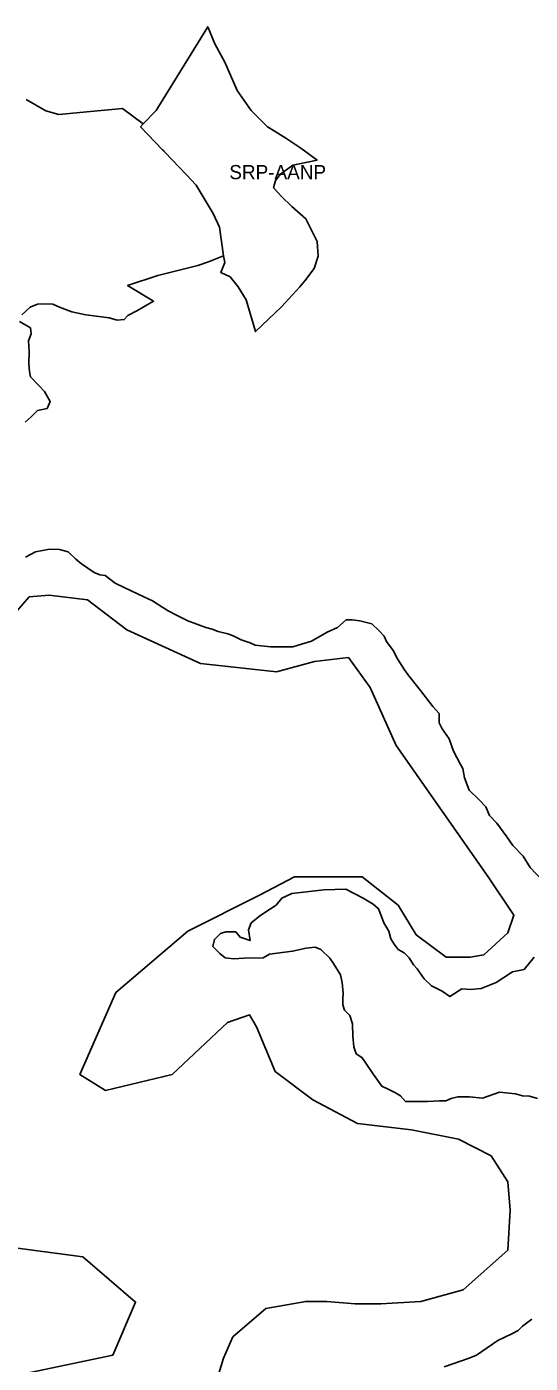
# Model space of a CAD drawing. Extents: x 598968 to 613553, y 4409678 to 4430833.
# Drawn here: x 604746 to 605173, y 4417266 to 4418399 of the extents above; entities that cross this region are included whole.
import ezdxf

# ---------------------------------------------------------------- set-up
doc = ezdxf.new("R2010")
doc.units = 0
for name, color, linetype in [('Sòl Rústic Comú', 7, 'Continuous'), ('Sòl Rústic Protegit', 7, 'Continuous'), ('Sòl Rústic Protegit - Alt Nivell de Protecció', 7, 'Continuous')]:
    doc.layers.add(name, color=color, linetype=linetype)

msp = doc.modelspace()

# ---------------------------------------------------------------- linework, layer by layer
at = {"layer": 'Sòl Rústic Comú'}
msp.add_lwpolyline([(604696.9791, 4417247.1936), (604818.6681, 4417272.6938), (604837.8559, 4417317.694), (604793.0431, 4417356.194), (604696.9797, 4417368.6938)], dxfattribs=at)
at = {"layer": 'Sòl Rústic Protegit'}
for points in [[(604745.1713, 4418337.1948), (604761.8589, 4418327.6948), (604772.7965, 4418324.6948), (604799.5469, 4418327.1948), (604826.7971, 4418329.6948), (604844.2347, 4418316.6948), (604855.3677, 4418328.0102), (604899.1177, 4418399.0102), (604905.1175, 4418384.5102), (604913.6801, 4418369.0102), (604923.9925, 4418345.0102), (604935.9927, 4418328.0102), (604949.7427, 4418314.0102), (604956.1633, 4418310.0588), (604965.1801, 4418304.5102), (604978.0551, 4418296.0102), (604985.3841, 4418290.6556), (604991.7427, 4418286.0102), (604974.0359, 4418282.1352), (604971.1799, 4418281.5102), (604960.8677, 4418274.0102), (604956.6177, 4418268.5102), (604954.8677, 4418262.5102), (604958.9113, 4418258.0988), (604961.7425, 4418255.0102), (604970.3051, 4418246.5102), (604982.3051, 4418236.0102), (604991.7427, 4418217.0102), (604992.6177, 4418204.5102), (604989.1801, 4418194.0102), (604981.4927, 4418183.5102), (604977.1799, 4418178.5102), (604961.7425, 4418161.5102), (604939.4299, 4418140.5102), (604931.6799, 4418167.5102), (604924.8677, 4418178.5102), (604917.9927, 4418187.0102), (604910.2427, 4418190.5102), (604913.6801, 4418199.0102), (604912.4851, 4418204.6948), (604899.7973, 4418199.6948), (604890.6097, 4418196.6948), (604856.7343, 4418188.1948), (604831.0465, 4418179.6948), (604853.1093, 4418166.1948), (604839.0465, 4418158.1948), (604831.2965, 4418154.1948), (604828.2965, 4418150.6946), (604822.3589, 4418150.1946), (604815.4839, 4418152.1946), (604795.7961, 4418154.6946), (604783.7959, 4418157.1946), (604773.3585, 4418161.1946), (604767.6709, 4418163.6946), (604761.4833, 4418164.1946), (604754.8583, 4418163.6946), (604748.5457, 4418161.1946), (604741.4831, 4418154.6946)], [(604741.4831, 4418154.6946), (604748.5457, 4418161.1946), (604754.8583, 4418163.6946), (604761.4833, 4418164.1946), (604767.6709, 4418163.6946), (604773.3585, 4418161.1946), (604783.7959, 4418157.1946), (604795.7961, 4418154.6946), (604815.4839, 4418152.1946), (604822.3589, 4418150.1946), (604828.2965, 4418150.6946), (604831.2965, 4418154.1948), (604839.0465, 4418158.1948), (604853.1093, 4418166.1948), (604831.0465, 4418179.6948), (604856.7343, 4418188.1948), (604890.6097, 4418196.6948), (604899.7973, 4418199.6948), (604912.4851, 4418204.6948), (604909.0475, 4418229.1948), (604903.8113, 4418240.7756), (604889.2975, 4418264.6948), (604881.0665, 4418273.3832), (604862.7125, 4418292.6684), (604861.9603, 4418293.4588), (604861.4329, 4418294.013), (604860.7945, 4418294.6838), (604842.1097, 4418314.1948), (604844.2347, 4418316.6948), (604826.7971, 4418329.6948), (604799.5469, 4418327.1948), (604772.7965, 4418324.6948), (604761.8589, 4418327.6948), (604745.1713, 4418337.1948)], [(604744.3577, 4418063.6944), (604749.2953, 4418068.1946), (604754.7953, 4418073.6946), (604762.7955, 4418075.1946), (604765.4205, 4418081.1946), (604760.6079, 4418089.6946), (604755.8579, 4418094.6946), (604748.8579, 4418102.1946), (604747.8579, 4418106.6946), (604747.4829, 4418113.1946), (604747.7955, 4418123.6946), (604747.0455, 4418132.6946), (604749.4205, 4418138.6946), (604748.9205, 4418143.6946), (604739.5455, 4418149.1946)], [(604739.5455, 4418149.1946), (604748.9205, 4418143.6946), (604749.4205, 4418138.6946), (604747.0455, 4418132.6946), (604747.7955, 4418123.6946), (604747.4829, 4418113.1946), (604747.8579, 4418106.6946), (604748.8579, 4418102.1946), (604755.8579, 4418094.6946), (604760.6079, 4418089.6946), (604765.4205, 4418081.1946), (604762.7955, 4418075.1946), (604754.7953, 4418073.6946), (604749.2953, 4418068.1946), (604744.3577, 4418063.6944)], [(605182.9859, 4417675.1948), (605172.5483, 4417686.1948), (605166.5483, 4417695.6948), (605157.7981, 4417704.6948), (605152.7357, 4417712.1948), (605144.2981, 4417723.6948), (605138.1105, 4417730.1948), (605134.7981, 4417737.6948), (605129.0481, 4417743.6948), (605120.7979, 4417751.6948), (605116.9229, 4417762.1948), (605115.3605, 4417770.1948), (605112.9855, 4417774.1948), (605107.3605, 4417784.6948), (605103.9229, 4417795.1948), (605097.7355, 4417803.6948), (605095.2979, 4417808.6948), (605095.2355, 4417816.6948), (605089.9229, 4417822.6948), (605079.5479, 4417836.1948), (605069.6729, 4417848.6948), (605065.9853, 4417853.6948), (605060.1103, 4417863.1948), (605056.2353, 4417870.1948), (605050.6727, 4417877.6948), (605048.7977, 4417882.1948), (605044.3601, 4417886.6948), (605038.1727, 4417892.6948), (605027.9225, 4417895.1948), (605021.4849, 4417896.1948), (605016.3599, 4417896.1948), (605009.1723, 4417889.6948), (605000.2347, 4417885.6946), (604986.9221, 4417878.1946), (604975.6719, 4417874.6946), (604971.2343, 4417873.1946), (604964.6093, 4417873.1946), (604952.2341, 4417873.1946), (604939.3591, 4417874.6946), (604935.0465, 4417876.6946), (604927.2965, 4417879.1946), (604920.6713, 4417882.6946), (604915.9839, 4417884.1946), (604908.0463, 4417886.1946), (604902.7337, 4417888.1946), (604897.5461, 4417889.6946), (604882.2961, 4417895.1946), (604872.6709, 4417900.1946), (604865.5459, 4417903.6946), (604860.9209, 4417906.6946), (604852.2957, 4417912.1946), (604844.7957, 4417915.6944), (604828.1081, 4417923.6944), (604820.5455, 4417927.1944), (604812.2329, 4417933.6944), (604807.4829, 4417934.1944), (604802.6703, 4417936.1944), (604792.1077, 4417943.6944), (604787.1077, 4417947.6944), (604780.7327, 4417953.6944), (604773.4827, 4417955.6944), (604764.9825, 4417956.1944), (604752.9199, 4417953.6944), (604744.6697, 4417949.1944)], [(604744.6697, 4417949.1944), (604752.9199, 4417953.6944), (604764.9825, 4417956.1944), (604773.4827, 4417955.6944), (604780.7327, 4417953.6944), (604787.1077, 4417947.6944), (604792.1077, 4417943.6944), (604802.6703, 4417936.1944), (604807.4829, 4417934.1944), (604812.2329, 4417933.6944), (604820.5455, 4417927.1944), (604828.1081, 4417923.6944), (604844.7957, 4417915.6944), (604852.2957, 4417912.1946), (604860.9209, 4417906.6946), (604865.5459, 4417903.6946), (604872.6709, 4417900.1946), (604882.2961, 4417895.1946), (604897.5461, 4417889.6946), (604902.7337, 4417888.1946), (604908.0463, 4417886.1946), (604915.9839, 4417884.1946), (604920.6713, 4417882.6946), (604927.2965, 4417879.1946), (604935.0465, 4417876.6946), (604939.3591, 4417874.6946), (604952.2341, 4417873.1946), (604964.6093, 4417873.1946), (604971.2343, 4417873.1946), (604975.6719, 4417874.6946), (604986.9221, 4417878.1946), (605000.2347, 4417885.6946), (605009.1723, 4417889.6948), (605016.3599, 4417896.1948), (605021.4849, 4417896.1948), (605027.9225, 4417895.1948), (605038.1727, 4417892.6948), (605044.3601, 4417886.6948), (605048.7977, 4417882.1948), (605050.6727, 4417877.6948), (605056.2353, 4417870.1948), (605060.1103, 4417863.1948), (605065.9853, 4417853.6948), (605069.6729, 4417848.6948), (605079.5479, 4417836.1948), (605089.9229, 4417822.6948), (605095.2355, 4417816.6948), (605095.2979, 4417808.6948), (605097.7355, 4417803.6948), (605103.9229, 4417795.1948), (605107.3605, 4417784.6948), (605112.9855, 4417774.1948), (605115.3605, 4417770.1948), (605116.9229, 4417762.1948), (605120.7979, 4417751.6948), (605129.0481, 4417743.6948), (605134.7981, 4417737.6948), (605138.1105, 4417730.1948), (605144.2981, 4417723.6948), (605152.7357, 4417712.1948), (605157.7981, 4417704.6948), (605166.5483, 4417695.6948), (605172.5483, 4417686.1948), (605182.9859, 4417675.1948)], [(604736.9821, 4417903.1944), (604747.7323, 4417915.6944), (604764.6073, 4417917.1944), (604797.1703, 4417913.1944), (604830.4829, 4417887.6944), (604893.0461, 4417859.1946), (604957.3591, 4417852.1946), (604989.4845, 4417860.6946), (605018.2973, 4417864.1946), (605036.8599, 4417838.6946), (605058.8599, 4417789.6946), (605136.7353, 4417678.1946), (605158.6729, 4417645.6946), (605153.6103, 4417630.6946), (605133.2975, 4417612.1946), (605121.4849, 4417610.1946), (605101.1723, 4417610.1946), (605075.7971, 4417629.1946), (605060.5469, 4417654.1946), (605030.1093, 4417678.1946), (605003.0465, 4417678.1944), (604972.6087, 4417678.1944), (604943.0457, 4417662.6944), (604882.1075, 4417632.1942), (604821.1691, 4417580.1942), (604790.6687, 4417510.694), (604812.4187, 4417497.194), (604869.0445, 4417510.6942), (604915.9201, 4417554.6942), (604934.3579, 4417561.1942), (604940.3579, 4417551.1942), (604956.2953, 4417513.1942), (604988.1705, 4417489.1942), (605025.9835, 4417469.1944), (605071.7963, 4417463.6944), (605111.6093, 4417455.6944), (605139.4845, 4417441.6944), (605153.4221, 4417419.6944), (605155.4219, 4417395.6944), (605153.4219, 4417361.6944), (605115.6089, 4417328.1944), (605079.7333, 4417318.1942), (605045.9205, 4417316.1942), (605023.9829, 4417316.1942), (605000.1075, 4417318.1942), (604982.1699, 4417318.1942), (604948.2945, 4417312.194), (604920.4191, 4417288.194), (604912.4815, 4417270.194), (604904.5437, 4417244.194)], [(604904.5437, 4417244.194), (604912.4815, 4417270.194), (604920.4191, 4417288.194), (604948.2945, 4417312.194), (604982.1699, 4417318.1942), (605000.1075, 4417318.1942), (605023.9829, 4417316.1942), (605045.9205, 4417316.1942), (605079.7333, 4417318.1942), (605115.6089, 4417328.1944), (605153.4219, 4417361.6944), (605155.4219, 4417395.6944), (605153.4221, 4417419.6944), (605139.4845, 4417441.6944), (605111.6093, 4417455.6944), (605071.7963, 4417463.6944), (605025.9835, 4417469.1944), (604988.1705, 4417489.1942), (604956.2953, 4417513.1942), (604940.3579, 4417551.1942), (604934.3579, 4417561.1942), (604915.9201, 4417554.6942), (604869.0445, 4417510.6942), (604812.4187, 4417497.194), (604790.6687, 4417510.694), (604821.1691, 4417580.1942), (604882.1075, 4417632.1942), (604943.0457, 4417662.6944), (604972.6087, 4417678.1944), (605003.0465, 4417678.1944), (605030.1093, 4417678.1946), (605060.5469, 4417654.1946), (605075.7971, 4417629.1946), (605101.1723, 4417610.1946), (605121.4849, 4417610.1946), (605133.2975, 4417612.1946), (605153.6103, 4417630.6946), (605158.6729, 4417645.6946), (605136.7353, 4417678.1946), (605058.8599, 4417789.6946), (605036.8599, 4417838.6946), (605018.2973, 4417864.1946), (604989.4845, 4417860.6946), (604957.3591, 4417852.1946), (604893.0461, 4417859.1946), (604830.4829, 4417887.6944), (604797.1703, 4417913.1944), (604764.6073, 4417917.1944), (604747.7323, 4417915.6944), (604736.9821, 4417903.1944)], [(605178.6725, 4417490.1946), (605171.7975, 4417492.1946), (605165.9849, 4417492.6946), (605159.9849, 4417494.1946), (605154.6099, 4417494.6946), (605146.3597, 4417495.6946), (605132.1721, 4417490.6944), (605121.1095, 4417491.6944), (605111.1093, 4417491.6944), (605105.4843, 4417490.1944), (605101.0467, 4417488.1944), (605095.5467, 4417488.1944), (605085.4841, 4417487.6944), (605079.7341, 4417487.6944), (605066.8589, 4417487.6944), (605062.4213, 4417492.6944), (605058.2963, 4417495.1944), (605051.9837, 4417498.1944), (605046.6087, 4417500.6944), (605039.6713, 4417510.6944), (605032.6711, 4417521.1944), (605029.8587, 4417525.1944), (605024.9837, 4417528.1944), (605022.8587, 4417534.1944), (605022.0461, 4417543.1944), (605021.7337, 4417553.6944), (605019.6711, 4417560.6944), (605015.1087, 4417565.1944), (605013.7337, 4417569.6944), (605013.7337, 4417574.6944), (605013.8587, 4417579.6944), (605013.0463, 4417588.6944), (605011.6713, 4417595.1944), (605005.6713, 4417604.6944), (605002.5461, 4417609.1944), (604994.9837, 4417616.6944), (604990.1087, 4417618.6944), (604982.4211, 4417617.6944), (604970.9833, 4417615.1944), (604951.4207, 4417612.6944), (604946.1081, 4417609.6944), (604929.9829, 4417609.1944), (604920.7953, 4417608.6944), (604913.9827, 4417609.6944), (604909.3577, 4417613.1944), (604903.4827, 4417619.1944), (604904.7953, 4417625.1944), (604909.8579, 4417630.1944), (604914.4829, 4417631.6944), (604922.8579, 4417631.6944), (604926.4829, 4417627.1944), (604934.9205, 4417624.1944), (604933.5455, 4417633.1944), (604935.9207, 4417639.1944), (604943.9833, 4417645.6944), (604952.1709, 4417651.1944), (604956.9833, 4417654.1944), (604961.8585, 4417660.1944), (604970.2961, 4417664.1944), (604997.5463, 4417667.1944), (605016.2965, 4417667.6946), (605030.9841, 4417660.1946), (605039.4217, 4417655.1946), (605043.8593, 4417651.1946), (605046.4217, 4417644.6946), (605048.4843, 4417639.1946), (605052.7343, 4417632.1946), (605054.2967, 4417625.6946), (605057.1719, 4417621.1946), (605060.5469, 4417616.6946), (605065.6719, 4417613.6946), (605069.9845, 4417609.6946), (605073.4845, 4417603.6946), (605076.6095, 4417600.1946), (605082.6719, 4417591.6946), (605088.7971, 4417585.6946), (605097.9221, 4417581.1946), (605104.3597, 4417576.6946), (605114.6097, 4417583.1946), (605121.9849, 4417582.6946), (605131.0475, 4417583.6946), (605143.5475, 4417588.6946), (605157.4853, 4417597.6946), (605167.2353, 4417599.6946), (605175.7355, 4417610.1946)], [(605175.7355, 4417610.1946), (605167.2353, 4417599.6946), (605157.4853, 4417597.6946), (605143.5475, 4417588.6946), (605131.0475, 4417583.6946), (605121.9849, 4417582.6946), (605114.6097, 4417583.1946), (605104.3597, 4417576.6946), (605097.9221, 4417581.1946), (605088.7971, 4417585.6946), (605082.6719, 4417591.6946), (605076.6095, 4417600.1946), (605073.4845, 4417603.6946), (605069.9845, 4417609.6946), (605065.6719, 4417613.6946), (605060.5469, 4417616.6946), (605057.1719, 4417621.1946), (605054.2967, 4417625.6946), (605052.7343, 4417632.1946), (605048.4843, 4417639.1946), (605046.4217, 4417644.6946), (605043.8593, 4417651.1946), (605039.4217, 4417655.1946), (605030.9841, 4417660.1946), (605016.2965, 4417667.6946), (604997.5463, 4417667.1944), (604970.2961, 4417664.1944), (604961.8585, 4417660.1944), (604956.9833, 4417654.1944), (604952.1709, 4417651.1944), (604943.9833, 4417645.6944), (604935.9207, 4417639.1944), (604933.5455, 4417633.1944), (604934.9205, 4417624.1944), (604926.4829, 4417627.1944), (604922.8579, 4417631.6944), (604914.4829, 4417631.6944), (604909.8579, 4417630.1944), (604904.7953, 4417625.1944), (604903.4827, 4417619.1944), (604909.3577, 4417613.1944), (604913.9827, 4417609.6944), (604920.7953, 4417608.6944), (604929.9829, 4417609.1944), (604946.1081, 4417609.6944), (604951.4207, 4417612.6944), (604970.9833, 4417615.1944), (604982.4211, 4417617.6944), (604990.1087, 4417618.6944), (604994.9837, 4417616.6944), (605002.5461, 4417609.1944), (605005.6713, 4417604.6944), (605011.6713, 4417595.1944), (605013.0463, 4417588.6944), (605013.8587, 4417579.6944), (605013.7337, 4417574.6944), (605013.7337, 4417569.6944), (605015.1087, 4417565.1944), (605019.6711, 4417560.6944), (605021.7337, 4417553.6944), (605022.0461, 4417543.1944), (605022.8587, 4417534.1944), (605024.9837, 4417528.1944), (605029.8587, 4417525.1944), (605032.6711, 4417521.1944), (605039.6713, 4417510.6944), (605046.6087, 4417500.6944), (605051.9837, 4417498.1944), (605058.2963, 4417495.1944), (605062.4213, 4417492.6944), (605066.8589, 4417487.6944), (605079.7341, 4417487.6944), (605085.4841, 4417487.6944), (605095.5467, 4417488.1944), (605101.0467, 4417488.1944), (605105.4843, 4417490.1944), (605111.1093, 4417491.6944), (605121.1095, 4417491.6944), (605132.1721, 4417490.6944), (605146.3597, 4417495.6946), (605154.6099, 4417494.6946), (605159.9849, 4417494.1946), (605165.9849, 4417492.6946), (605171.7975, 4417492.1946), (605178.6725, 4417490.1946)], [(604696.9797, 4417368.6938), (604793.0431, 4417356.194), (604837.8559, 4417317.694), (604818.6681, 4417272.6938), (604696.9791, 4417247.1936)], [(605099.5459, 4417262.6942), (605120.6711, 4417270.1942), (605127.0463, 4417272.6942), (605144.9215, 4417285.1944), (605156.9215, 4417290.6944), (605162.3591, 4417293.6944), (605165.9217, 4417297.1944), (605173.9843, 4417303.1944)], [(605173.9843, 4417303.1944), (605165.9217, 4417297.1944), (605162.3591, 4417293.6944), (605156.9215, 4417290.6944), (605144.9215, 4417285.1944), (605127.0463, 4417272.6942), (605120.6711, 4417270.1942), (605099.5459, 4417262.6942)]]:
    msp.add_lwpolyline(points, dxfattribs=at)
at = {"layer": 'Sòl Rústic Protegit - Alt Nivell de Protecció'}
msp.add_lwpolyline([(604912.4851, 4418204.6948), (604913.6801, 4418199.0102), (604910.2427, 4418190.5102), (604917.9927, 4418187.0102), (604924.8677, 4418178.5102), (604931.6799, 4418167.5102), (604939.4299, 4418140.5102), (604961.7425, 4418161.5102), (604977.1799, 4418178.5102), (604981.4927, 4418183.5102), (604989.1801, 4418194.0102), (604992.6177, 4418204.5102), (604991.7427, 4418217.0102), (604982.3051, 4418236.0102), (604970.3051, 4418246.5102), (604961.7425, 4418255.0102), (604958.9113, 4418258.0988), (604954.8677, 4418262.5102), (604956.6177, 4418268.5102), (604960.8677, 4418274.0102), (604971.1799, 4418281.5102), (604974.0359, 4418282.1352), (604991.7427, 4418286.0102), (604985.3841, 4418290.6556), (604978.0551, 4418296.0102), (604965.1801, 4418304.5102), (604956.1633, 4418310.0588), (604949.7427, 4418314.0102), (604935.9927, 4418328.0102), (604923.9925, 4418345.0102), (604913.6801, 4418369.0102), (604905.1175, 4418384.5102), (604899.1177, 4418399.0102), (604855.3677, 4418328.0102), (604844.2347, 4418316.6948), (604842.1097, 4418314.1948), (604860.7945, 4418294.6838), (604861.4329, 4418294.013), (604861.9603, 4418293.4588), (604862.7125, 4418292.6684), (604881.0665, 4418273.3832), (604889.2975, 4418264.6948), (604903.8113, 4418240.7756), (604909.0475, 4418229.1948)], close=True, dxfattribs=at)

# ---------------------------------------------------------------- texts
msp.add_text('SRP-AANP', height=12, dxfattribs=at).set_placement((604917.3637, 4418269.7602))

doc.saveas('drawing.dxf')
